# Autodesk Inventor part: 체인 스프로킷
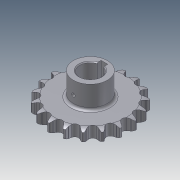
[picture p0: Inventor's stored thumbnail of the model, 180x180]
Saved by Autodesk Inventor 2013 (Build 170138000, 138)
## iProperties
Created: 2014-07
Part Number: 체인 스프로킷
Material: 강
Document SubType Name: Modeling
Designer: KYOUNG IL JANG
Density: 7.85 g/cm^3
Mass: 738.626 g
Surface Area: 236.854 cm^2
Volume: 94.0925 cm^3
CustomPartVersion: 1
Company: 한국ATC센터
Author: KYOUNG IL JANG
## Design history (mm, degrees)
sketch "이론적 톱니 프로파일"
  geometry: L1 (0, 0)-(0, 45.567); L2 (0, 0)-(14.795, 43.098); L3 (0, 45.567)-(14.795, 43.098); L4 (0, 45.567)-(5.661, 50.015); L5 (5.661, 50.015)-(-5.141, 45.406); L6 (-12.428, 43.493)-(-5.573, 46.417); L7 (-5.141, 45.406)-(-5.573, 46.417); L8 (5.573, 46.417)-(5.141, 45.406); L9 (0, 0)-(8.138, 48.771); A1 r 45.567 centre (0, 0) between (0, 45.567) and (14.795, 43.098); A2 r 49.445 centre (0, 0) between (7.302, 48.903) and (-7.302, 48.903); A3 r 4.545 centre (0, 45.567) between (-3.574, 42.758) and (3.574, 42.758); A4 r 7.453 centre (12.428, 43.493) between (7.302, 48.903) and (5.573, 46.417); A5 r 7.453 centre (-12.428, 43.493) between (-5.573, 46.417) and (-7.302, 48.903); A6 r 11.745 centre (5.661, 50.015) between (-5.141, 45.406) and (-3.574, 42.758); A7 r 11.745 centre (-5.661, 50.015) between (3.574, 42.758) and (5.141, 45.406); 2 further points
  constraints: 18 end point, 15 point on circle, 7 centre point, 3 coincident, 3 point on line, 3 symmetric about line, 3 tangent, 1 equal radius, 1 midpoint, 1 parallel, 1 vertical, 1 other
  dimensions: "d0" = 91.13301 diameter of A1 (computed from da_p, da_z); "d2" = 18.9474 deg angle of L2 L1 (computed from da_z); "d3" = 4.545 radius of A3 (= 0.5 x da_Dr + da_SC); "d10" = 128.158 deg angle of L4 L1 (computed from da_z); "d11" = 15.0526 deg angle of L5 L4 (computed from da_z); "d12" = 7.2 distance of L3.start L4.end (= 0.8 x da_Dr); "d13" = 11.745 distance of L4.end L5.end (= 1.3 x da_Dr + da_SC); "d14" = 12.6 distance of A4.centre L1.end (= 1.4 x da_Dr); "d23" = 4.5 distance from line of L9.end L3 (= da_Ha)
sketch "톱니 프로파일"
  geometry: L1 (0, 0)-(0, 45.567); L2 (0, 45.567)-(4.203, 43.837); L3 (0, 45.567)-(-4.203, 43.837); A1 r 4.545 centre (0, 45.567) between (-4.203, 43.837) and (4.203, 43.837); A2 r 22.68 centre (25.176, 35.206) between (7.12, 48.93) and (4.203, 43.837); A3 r 22.68 centre (-25.176, 35.206) between (-4.203, 43.837) and (-7.12, 48.93); A4 r 49.445 centre (0, 0) between (-7.12, 48.93) and (7.12, 48.93) reference; 1 further point
  constraints: 9 point on circle, 6 end point, 3 centre point, 2 tangent, 1 coincident, 1 equal radius, 1 vertical, 1 other
  dimensions: "d44" = 135.263 deg angle of L3 L2 (= da_Alfa); "d45" = 22.68 radius of A2 (= da_Re); "d46" = 4.545 radius of A1 (= da_Ri)
sketch "단면 프로파일"
  geometry: L1 (49.445, 0)-(-49.445, 0) reference; L2 (33.265, 6.65)-(-33.265, 6.65); L3 (-33.265, 6.65)-(-33.265, -6.65); L4 (-33.265, -6.65)-(33.265, -6.65); L5 (33.265, -6.65)-(33.265, 6.65); L6 (33.265, 6.65)-(49.445, 6.65); L7 (49.445, 6.65)-(49.445, -6.65); L8 (49.445, -6.65)-(33.265, -6.65); L9 (33.265, -6.65)-(33.265, 6.65); L10 (42.183, 6.65)-(0, 6.65); L11 (0, 6.65)-(0, -6.65); L12 (0, -6.65)-(42.183, -6.65); L13 (0, 6.65)-(0, -6.65); L14 (49.445, 4.775)-(49.445, -4.775); A1 r 15 centre (42.183, -8.35) between (49.445, 4.775) and (42.183, 6.65); A2 r 15 centre (42.183, 8.35) between (42.183, -6.65) and (49.445, -4.775); 2 further points
  constraints: 26 end point, 7 midpoint, 5 perpendicular, 4 parallel, 4 point on circle, 3 point on line, 3 symmetric about line, 2 centre point, 2 horizontal, 2 tangent, 1 collinear, 1 other
  dimensions: "d30" = 13.3 distance between parallel lines of L8 L6 (= da_Bf); "d31" = 66.53007 distance between parallel lines of L3 L5 (= da_Ds); "d32" = 13.3 distance between parallel lines of L4 L2 (= da_Bs); "d33" = 1.875 distance from line of L14.start L6 (= da_Ba); "d34" = 15 radius of A1 (= da_Rx); "d43" = 6.65 distance between parallel lines of L4 L1 (computed from da_k, da_pt, da_Bs)
revolve "슈라우드" stored, may be unused: angle "d36" = 90 deg
revolve "스트랜드" stored, may be unused: angle "d37" = 90 deg
extrude "이론적 톱니" cut sketch "이론적 톱니 프로파일" stored distance "d18" = 10; taper "d19" = 0 deg; dims "d49" = 0, "form_type" = 0 [user parameter]
extrude "톱니" cut sketch "톱니 프로파일" stored distance "d47" = 10; taper "d48" = 0 deg; dims "d50" = 10, "form_type" = 0 [user parameter]
node "타이밍 평면"
node "작업 평면3"
sketch "스케치5"
  geometry: C1 r 20 at (0, -45.567); 1 further point
  constraints: 1 centre point, 1 coincident
  dimensions: "d52" = 40 diameter of C1
extrude "돌출4" join sketch "스케치5" stored distance "d53" = 10; taper "d54" = 0 deg
sketch "스케치6"
  geometry: L1 (4, 11.843)-(4, 16.5); L2 (4, 16.5)-(-4, 16.5); L3 (-4, 16.5)-(-4, 11.843); A1 r 12.5 centre (0, 0) between (4, 11.843) and (-4, 11.843); 1 further point
  constraints: 6 end point, 2 parallel, 2 point on circle, 1 centre point, 1 coincident, 1 perpendicular, 1 vertical
  dimensions: "d55" = 25 diameter of A1; "d56" = 29 dimension on A1 L2 (computed from d55); "d57" = 8 distance of L1.end L2.end
extrude "돌출5" cut sketch "스케치6" stored distance "d58" = 10; taper "d59" = 0 deg
fillet "모깎기2" dims "d60" = 3
chamfer "모따기1" distance "d61" = 1; stored, may be unused: second distance "d62" = 2, angle "d63" = 45 deg
node "작업 평면4"
sketch "스케치7"
  geometry: L1 (-13.5, -13.3)-(13.5, -13.3) reference; 4 further points
  constraints: 1 vertical alignment
  dimensions: "d65" = 25 distance from line of point (0, 11.7) L1
hole "구멍1" sketch "스케치7" at (0, 11.7) diameter "d66" = 4.134; stored, may be unused: countersink angle "d70" = 90 deg, drill point angle "d72" = 118 deg; dims "d67" = 6, "d68" = 4, "d69" = 2, "d71" = 8
body "Solid1"
pattern_linear "스트랜드 패턴" dims "d40" = 24 (= da_pt)
pattern_circular "톱니 패턴" dims angle "d21" = 360 deg
other parameters: "da_p" = 15 [user parameter; used in 1 equation term], "da_Dr" = 9 [user parameter; used in 4 equation terms], "da_SC" = 0.045 [user parameter; used in 2 equation terms], "da_Ha" = 4.5 [user parameter; used in 1 equation term], "da_pt" = 24 [user parameter; used in 2 equation terms], "da_Bf" = 13.3 [user parameter; used in 1 equation term], "d28" = 0, "d29" = 0, "da_Ba" = 1.875 [user parameter; used in 1 equation term], "da_Rx" = 15 [user parameter; used in 1 equation term], "da_Ra" = 0.6 [user parameter], "da_Bs" = 13.3 [user parameter; used in 2 equation terms], "da_Ds" = 66.53007 [user parameter; used in 1 equation term], "d42" = 0, "da_Re" = 22.68 [user parameter; used in 1 equation term], "da_Ri" = 4.545 [user parameter; used in 1 equation term], "da_Alfa" = 135.263 deg [user parameter; used in 1 equation term]
